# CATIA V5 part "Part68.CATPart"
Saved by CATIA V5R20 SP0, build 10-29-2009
Part number: FA 042200-3
Revision: ANY
Definition: UNKNOWN
Nomenclature: FA 042200-3
Source: Unknown
Bounding box of the stored display mesh (mm): x 0 to 2, y -1.45 to 1.45, z -1.45 to 1.45
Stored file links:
  C:\Users\Utente\Desktop\IO LAVORO\3D X SITO CF\CUMSA\3D files FA\FA 053000\Part68.CATPart

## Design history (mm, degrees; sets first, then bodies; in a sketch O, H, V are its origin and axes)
Body1 "Revolución1" (main body)
  Solid1: solid without history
